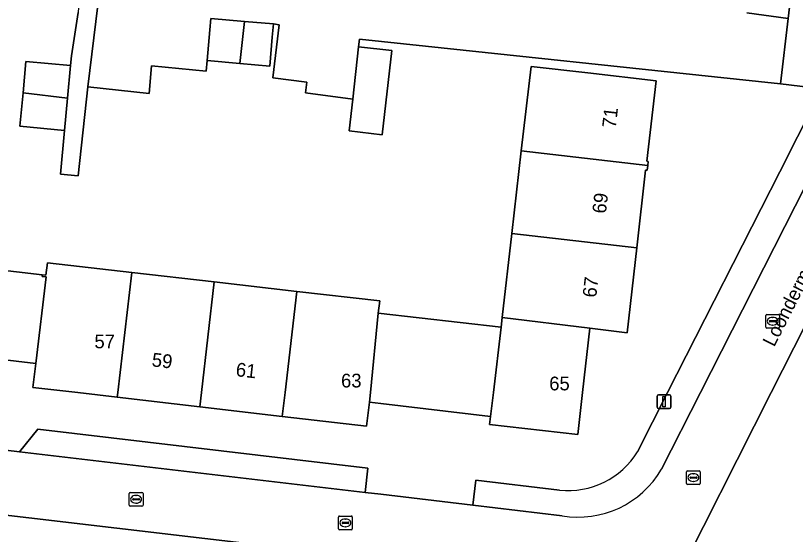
# Model space of a CAD drawing. Extents: x 161241 to 161758, y 384138 to 384885.
# Drawn here: x 161473.4 to 161530.1, y 384489.7 to 384527.4 of the extents above; entities that cross this region are included whole.
import ezdxf

# ---------------------------------------------------------------- set-up
doc = ezdxf.new("R2010")
doc.units = 0
for name, color, linetype in [('IMGEO_Erf', 7, 'Continuous'), ('IMGEO_Kolk', 7, 'Continuous'), ('IMGEO_Lichtmast', 7, 'Continuous'), ('IMGEO_Openbare_ruimte_label', 7, 'Continuous'), ('IMGEO_Pand', 7, 'Continuous'), ('IMGEO_Pand_nummerreeks', 7, 'Continuous'), ('IMGEO_Parkeervlak_open', 7, 'Continuous'), ('IMGEO_Rijbaan_lokaal_open', 7, 'Continuous'), ('IMGEO_Voetpad_open', 7, 'Continuous')]:
    doc.layers.add(name, color=color, linetype=linetype)

msp = doc.modelspace()

# ---------------------------------------------------------------- linework, layer by layer
at = {"layer": 'IMGEO_Erf'}
for points in [[(161523.254, 384566.865), (161544.482, 384564.358), (161544.805, 384567.256), (161545.138, 384570.12), (161546.893, 384585.147), (161552.363, 384584.51), (161557.347, 384583.93), (161554.934, 384563.149), (161549.997, 384563.724), (161547.01, 384536.791), (161539.084, 384521.135), (161528.385, 384500), (161520.975, 384485.363), (161514.621, 384486.15), (161513.81, 384486.25), (161510.292, 384449.829)], [(161526.614, 384527.621), (161529.608, 384527.209), (161533.354, 384558.711)], [(161497.948, 384521.353), (161494.507, 384521.807), (161494.61, 384522.581), (161492.139, 384522.907), (161492.609, 384526.767), (161492.185, 384526.819), (161492.101, 384525.868), (161491.915, 384523.761), (161489.736, 384523.954), (161487.362, 384524.164), (161487.293, 384523.385), (161483.32, 384523.775), (161483.162, 384521.753), (161478.689, 384522.238), (161477.99, 384515.77), (161476.699, 384515.881), (161477.002, 384519.077), (161473.757, 384519.376), (161473.981, 384521.799), (161474.192, 384524.085), (161477.437, 384523.786), (161477.504, 384524.509), (161477.986, 384527.66)], [(161518.656, 384495.69), (161520.844, 384500), (161528.997, 384516.063), (161530.289, 384518.608), (161532.06, 384522.097), (161529.045, 384522.471), (161498.44, 384525.706), (161498.381, 384525.152), (161500.794, 384524.877), (161500.097, 384518.765), (161497.684, 384519.04), (161497.948, 384521.353)], [(161466.833, 384509.551), (161475.383, 384508.568), (161475.645, 384508.538), (161475.751, 384509.452), (161481.888, 384508.746), (161487.887, 384508.056), (161493.887, 384507.366), (161499.919, 384506.672), (161499.806, 384505.78), (161508.732, 384504.753), (161508.814, 384505.467), (161509.517, 384511.579), (161510.209, 384517.593), (161510.915, 384523.734), (161515.039, 384523.257), (161520.008, 384522.683), (161519.33, 384516.828), (161519.434, 384516.821), (161519.396, 384516.532), (161519.349, 384516.181), (161519.244, 384516.192), (161518.598, 384510.53), (161517.893, 384504.356), (161515.201, 384504.684), (161514.662, 384500), (161514.31, 384496.94), (161507.907, 384497.678), (161507.972, 384498.271), (161500, 384499.202), (161499.16, 384499.3), (161498.958, 384497.553), (161492.829, 384498.268), (161486.83, 384498.967), (161480.832, 384499.666), (161477.97, 384500), (161474.702, 384500.381), (161474.911, 384502.113), (161466.108, 384503.152)], [(161456.261, 384497.821), (161473.721, 384495.685), (161475.066, 384497.328), (161499.057, 384494.509), (161498.849, 384492.738), (161500, 384492.603), (161506.677, 384491.817), (161506.891, 384493.621), (161512.994, 384492.896)]]:
    msp.add_lwpolyline(points, dxfattribs=at)
msp.add_arc((161513.606, 384498.79), 5.925, 264.0718, 328.4576, dxfattribs=at)
at = {"layer": 'IMGEO_Kolk'}
for p, q in [((161528.06, 384505.69), (161528.912, 384505.69)), ((161527.985, 384504.764), (161527.985, 384505.616)), ((161528.244, 384505.184), (161528.244, 384505.196)), ((161528.682, 384505.147), (161528.284, 384505.147)), ((161528.287, 384505.233), (161528.685, 384505.233)), ((161528.473, 384505.47), (161528.498, 384505.47)), ((161528.728, 384505.196), (161528.728, 384505.184)), ((161528.986, 384505.616), (161528.986, 384504.764)), ((161528.912, 384504.69), (161528.06, 384504.69)), ((161528.496, 384504.91), (161528.471, 384504.91)), ((161522.219, 384493.388), (161522.219, 384494.24)), ((161522.294, 384494.314), (161523.146, 384494.314)), ((161522.478, 384493.808), (161522.478, 384493.82)), ((161522.521, 384493.857), (161522.919, 384493.857)), ((161522.707, 384494.094), (161522.732, 384494.094)), ((161522.962, 384493.82), (161522.962, 384493.808)), ((161523.22, 384494.24), (161523.22, 384493.388)), ((161523.146, 384493.314), (161522.294, 384493.314)), ((161522.916, 384493.771), (161522.518, 384493.771)), ((161522.73, 384493.534), (161522.705, 384493.534)), ((161481.702, 384491.81), (161481.702, 384492.662)), ((161481.777, 384492.736), (161482.629, 384492.736)), ((161482.703, 384492.662), (161482.703, 384491.81)), ((161481.961, 384492.23), (161481.961, 384492.242)), ((161482.399, 384492.193), (161482.001, 384492.193)), ((161482.004, 384492.279), (161482.402, 384492.279)), ((161482.19, 384492.516), (161482.215, 384492.516)), ((161482.445, 384492.242), (161482.445, 384492.23)), ((161482.629, 384491.736), (161481.777, 384491.736)), ((161482.213, 384491.956), (161482.188, 384491.956)), ((161496.995, 384491.019), (161497.847, 384491.019)), ((161496.92, 384490.093), (161496.92, 384490.945)), ((161497.179, 384490.513), (161497.179, 384490.525)), ((161497.617, 384490.476), (161497.219, 384490.476)), ((161497.222, 384490.562), (161497.62, 384490.562)), ((161497.408, 384490.799), (161497.433, 384490.799)), ((161497.663, 384490.525), (161497.663, 384490.513)), ((161497.921, 384490.945), (161497.921, 384490.093)), ((161497.847, 384490.019), (161496.995, 384490.019)), ((161497.431, 384490.239), (161497.406, 384490.239))]:
    msp.add_line(p, q, dxfattribs=at)
for points in [[(161528.06, 384505.69), (161528.912, 384505.69)], [(161527.985, 384504.764), (161527.985, 384505.616)], [(161528.986, 384505.616), (161528.986, 384504.764)], [(161528.912, 384504.69), (161528.06, 384504.69)], [(161522.219, 384493.388), (161522.219, 384494.24)], [(161522.294, 384494.314), (161523.146, 384494.314)], [(161523.22, 384494.24), (161523.22, 384493.388)], [(161523.146, 384493.314), (161522.294, 384493.314)], [(161481.702, 384491.81), (161481.702, 384492.662)], [(161481.777, 384492.736), (161482.629, 384492.736)], [(161482.703, 384492.662), (161482.703, 384491.81)], [(161482.629, 384491.736), (161481.777, 384491.736)], [(161496.995, 384491.019), (161497.847, 384491.019)], [(161496.92, 384490.093), (161496.92, 384490.945)], [(161497.921, 384490.945), (161497.921, 384490.093)], [(161497.847, 384490.019), (161496.995, 384490.019)]]:
    msp.add_lwpolyline(points, dxfattribs=at)
for centre, radius, start, end in [((161528.062, 384505.614), 0.0765, 91.552, 178.448), ((161528.062, 384505.614), 0.0765, 91.552, 178.448), ((161528.91, 384505.614), 0.0765, 1.552, 88.448), ((161528.91, 384505.614), 0.0765, 1.552, 88.448), ((161528.284, 384505.193), 0.0403, 85.8775, 175.7526), ((161528.281, 384505.183), 0.0366, 178.938, 274.7102), ((161528.685, 384505.19), 0.043, 264.8664, 352.4533), ((161528.689, 384505.195), 0.0386, 1.7309, 96.639), ((161528.062, 384504.766), 0.0765, 181.552, 268.448), ((161528.062, 384504.766), 0.0765, 181.552, 268.448), ((161528.91, 384504.766), 0.0765, 271.552, 358.448), ((161528.91, 384504.766), 0.0765, 271.552, 358.448), ((161522.296, 384494.238), 0.0765, 91.552, 178.448), ((161522.296, 384494.238), 0.0765, 91.552, 178.448), ((161522.518, 384493.817), 0.0403, 85.8775, 175.7526), ((161522.515, 384493.807), 0.0366, 178.938, 274.7102), ((161522.919, 384493.814), 0.043, 264.8664, 352.4533), ((161522.923, 384493.819), 0.0386, 1.7309, 96.639), ((161523.144, 384494.238), 0.0765, 1.552, 88.448), ((161523.144, 384494.238), 0.0765, 1.552, 88.448), ((161522.296, 384493.39), 0.0765, 181.552, 268.448), ((161522.296, 384493.39), 0.0765, 181.552, 268.448), ((161523.144, 384493.39), 0.0765, 271.552, 358.448), ((161523.144, 384493.39), 0.0765, 271.552, 358.448), ((161481.779, 384492.66), 0.0765, 91.552, 178.448), ((161481.779, 384492.66), 0.0765, 91.552, 178.448), ((161482.627, 384492.66), 0.0765, 1.552, 88.448), ((161482.627, 384492.66), 0.0765, 1.552, 88.448), ((161482.001, 384492.239), 0.0403, 85.8775, 175.7526), ((161481.998, 384492.229), 0.0366, 178.938, 274.7102), ((161482.402, 384492.236), 0.043, 264.8664, 352.4533), ((161482.406, 384492.241), 0.0386, 1.7309, 96.639), ((161481.779, 384491.812), 0.0765, 181.552, 268.448), ((161481.779, 384491.812), 0.0765, 181.552, 268.448), ((161482.627, 384491.812), 0.0765, 271.552, 358.448), ((161482.627, 384491.812), 0.0765, 271.552, 358.448), ((161496.997, 384490.943), 0.0765, 91.552, 178.448), ((161496.997, 384490.943), 0.0765, 91.552, 178.448), ((161497.845, 384490.943), 0.0765, 1.552, 88.448), ((161497.845, 384490.943), 0.0765, 1.552, 88.448), ((161497.219, 384490.522), 0.0403, 85.8775, 175.7526), ((161497.216, 384490.512), 0.0366, 178.938, 274.7102), ((161497.62, 384490.519), 0.043, 264.8664, 352.4533), ((161497.624, 384490.524), 0.0386, 1.7309, 96.639), ((161496.997, 384490.095), 0.0765, 181.552, 268.448), ((161496.997, 384490.095), 0.0765, 181.552, 268.448), ((161497.845, 384490.095), 0.0765, 271.552, 358.448), ((161497.845, 384490.095), 0.0765, 271.552, 358.448)]:
    msp.add_arc(centre, radius, start, end, dxfattribs=at)
for centre, major_axis, ratio, start_param, end_param in [((161528.472, 384505.19), (-0.387, 0.002), 0.722429, 4.712389, 7.853982), ((161528.497, 384505.19), (-0.39, 0.002), 0.717154, 1.570796, 4.712389), ((161522.706, 384493.814), (-0.387, 0.002), 0.722429, 4.712389, 7.853982), ((161522.731, 384493.814), (-0.39, 0.002), 0.717154, 1.570796, 4.712389), ((161482.189, 384492.236), (-0.387, 0.002), 0.722429, 4.712389, 7.853982), ((161482.214, 384492.236), (-0.39, 0.002), 0.717154, 1.570796, 4.712389), ((161497.407, 384490.519), (-0.387, 0.002), 0.722429, 4.712389, 7.853982), ((161497.432, 384490.519), (-0.39, 0.002), 0.717154, 1.570796, 4.712389)]:
    msp.add_ellipse(centre, major_axis=major_axis, ratio=ratio, start_param=start_param, end_param=end_param, dxfattribs=at)
at = {"layer": 'IMGEO_Lichtmast'}
for p, q in [((161520.087, 384498.933), (161520.087, 384499.733)), ((161520.087, 384499.733), (161520.087, 384498.933)), ((161520.187, 384499.833), (161520.977, 384499.833)), ((161520.977, 384499.833), (161520.187, 384499.833)), ((161521.077, 384499.733), (161521.077, 384498.933)), ((161521.077, 384498.933), (161521.077, 384499.733)), ((161520.977, 384498.833), (161520.187, 384498.833)), ((161520.187, 384498.833), (161520.977, 384498.833))]:
    msp.add_line(p, q, dxfattribs=at)
msp.add_lwpolyline([(161520.507, 384499.708), (161520.657, 384499.708), (161520.657, 384498.958), (161520.507, 384498.958), (161520.507, 384499.708)], dxfattribs=at)
for centre, start, end in [((161520.187, 384499.733), 90, 180), ((161520.187, 384499.733), 90, 180), ((161520.977, 384499.733), 0, 90), ((161520.977, 384499.733), 360, 90), ((161520.187, 384498.933), 180, 270), ((161520.187, 384498.933), 180, 270), ((161520.977, 384498.933), 270, 0), ((161520.977, 384498.933), 270, 0)]:
    msp.add_arc(centre, 0.1, start, end, dxfattribs=at)
at = {"layer": 'IMGEO_Pand'}
for points in [[(161490.091, 384527.004), (161487.632, 384527.222), (161487.558, 384526.386), (161487.362, 384524.164), (161489.736, 384523.954)], [(161492.101, 384525.868), (161492.185, 384526.819), (161490.091, 384527.004), (161489.736, 384523.954), (161491.915, 384523.761)], [(161500.794, 384524.877), (161498.381, 384525.152), (161497.948, 384521.353), (161497.684, 384519.04), (161500.097, 384518.765)], [(161477.437, 384523.786), (161474.192, 384524.085), (161473.981, 384521.799), (161477.219, 384521.424)], [(161519.396, 384516.532), (161519.434, 384516.821), (161519.33, 384516.828), (161520.008, 384522.683), (161515.039, 384523.257), (161510.915, 384523.734), (161510.209, 384517.593)], [(161473.757, 384519.376), (161477.002, 384519.077), (161477.219, 384521.424), (161473.981, 384521.799)], [(161510.209, 384517.593), (161509.517, 384511.579), (161518.598, 384510.53), (161519.244, 384516.192), (161519.349, 384516.181), (161519.396, 384516.532)], [(161515.201, 384504.684), (161517.893, 384504.356), (161518.598, 384510.53), (161509.517, 384511.579), (161508.814, 384505.467)], [(161475.383, 384508.568), (161466.833, 384509.551), (161466.108, 384503.152), (161474.911, 384502.113), (161475.672, 384508.413), (161475.37, 384508.45)], [(161475.37, 384508.45), (161475.672, 384508.413), (161474.911, 384502.113), (161474.702, 384500.381), (161477.97, 384500), (161480.832, 384499.666), (161480.871, 384500), (161481.888, 384508.746), (161475.751, 384509.452), (161475.645, 384508.538), (161475.383, 384508.568)], [(161480.832, 384499.666), (161486.83, 384498.967), (161486.95, 384500), (161487.887, 384508.056), (161481.888, 384508.746), (161480.871, 384500)], [(161493.887, 384507.366), (161487.887, 384508.056), (161486.95, 384500), (161486.83, 384498.967), (161492.829, 384498.268), (161493.03, 384500)], [(161493.03, 384500), (161492.829, 384498.268), (161498.958, 384497.553), (161499.16, 384499.3), (161499.235, 384500), (161499.806, 384505.78), (161499.919, 384506.672), (161493.887, 384507.366)], [(161508.177, 384500), (161508.732, 384504.753), (161499.806, 384505.78), (161499.235, 384500), (161499.16, 384499.3), (161500, 384499.202), (161507.972, 384498.271)], [(161507.972, 384498.271), (161507.907, 384497.678), (161514.31, 384496.94), (161514.662, 384500), (161515.201, 384504.684), (161508.814, 384505.467), (161508.732, 384504.753), (161508.177, 384500)]]:
    msp.add_lwpolyline(points, close=True, dxfattribs=at)
at = {"layer": 'IMGEO_Parkeervlak_open'}
msp.add_lwpolyline([(161498.849, 384492.738), (161499.057, 384494.509), (161475.066, 384497.328), (161473.721, 384495.685)], close=True, dxfattribs=at)
at = {"layer": 'IMGEO_Rijbaan_lokaal_open'}
msp.add_lwpolyline([(161549.997, 384563.724), (161552.363, 384584.51), (161546.893, 384585.147), (161545.138, 384570.12), (161544.805, 384567.256), (161544.482, 384564.358), (161544.235, 384562.197), (161526.561, 384564.282), (161512.889, 384565.866), (161500, 384567.378), (161464.869, 384571.501), (161464.362, 384566.766), (161482.25, 384564.675), (161500, 384562.593), (161511.694, 384561.211), (161511.799, 384561.199), (161533.354, 384558.711), (161529.608, 384527.209), (161529.045, 384522.471), (161532.06, 384522.097), (161534.304, 384521.808), (161539.084, 384521.135), (161547.01, 384536.791)], close=True, dxfattribs=at)
for points in [[(161480.018, 384533.151), (161478.689, 384522.238), (161483.162, 384521.753), (161483.32, 384523.775), (161487.293, 384523.385), (161487.362, 384524.164), (161487.558, 384526.386), (161487.632, 384527.222), (161490.091, 384527.004), (161492.185, 384526.819), (161492.609, 384526.767), (161492.139, 384522.907), (161494.61, 384522.581), (161494.507, 384521.807), (161497.948, 384521.353), (161498.381, 384525.152), (161498.44, 384525.706), (161529.045, 384522.471), (161529.608, 384527.209), (161526.614, 384527.621)], [(161539.084, 384521.135), (161534.304, 384521.808), (161532.188, 384517.643), (161530.896, 384515.099), (161523.226, 384500), (161520.396, 384494.429)], [(161513.174, 384491.028), (161506.677, 384491.817), (161500, 384492.603), (161498.849, 384492.738), (161473.721, 384495.685), (161456.261, 384497.821), (161442.259, 384499.359), (161436.769, 384500), (161430.603, 384500.72), (161430.519, 384500), (161430.062, 384496.065), (161448.776, 384493.891), (161500, 384487.889), (161510.654, 384486.641), (161513.81, 384486.25), (161514.621, 384486.15), (161520.975, 384485.363), (161528.385, 384500), (161539.084, 384521.135)]]:
    msp.add_lwpolyline(points, dxfattribs=at)
msp.add_arc((161514.325, 384497.952), 7.019, 260.5591, 329.8745, dxfattribs=at)
at = {"layer": 'IMGEO_Voetpad_open'}
for points in [[(161480.018, 384533.151), (161480.929, 384533.054), (161481.372, 384536.621), (161481.755, 384539.706), (161479.365, 384539.957), (161479.31, 384539.433), (161479.067, 384537.13), (161478.149, 384529.998), (161478.133, 384529.762), (161477.986, 384527.66), (161477.504, 384524.509), (161477.437, 384523.786), (161477.219, 384521.424), (161477.002, 384519.077), (161476.699, 384515.881), (161477.99, 384515.77), (161478.689, 384522.238)], [(161430.062, 384496.065), (161427.321, 384496.383), (161396.178, 384500), (161357.097, 384504.581), (161354.376, 384504.9), (161340.82, 384506.489), (161340.647, 384506.515), (161340.403, 384504.377), (161341.704, 384504.225), (161377.935, 384500), (161395.453, 384497.957), (161401.111, 384497.3), (161421.466, 384494.929), (161433, 384493.585), (161437.975, 384493.006), (161442.515, 384492.47), (161448.511, 384491.779), (161454.323, 384491.094), (161500, 384485.79), (161510.344, 384484.589), (161510.654, 384486.641), (161500, 384487.889), (161448.776, 384493.891)]]:
    msp.add_lwpolyline(points, close=True, dxfattribs=at)
for points in [[(161534.304, 384521.808), (161532.06, 384522.097), (161530.289, 384518.608), (161528.997, 384516.063), (161520.844, 384500), (161518.656, 384495.69)], [(161520.396, 384494.429), (161523.226, 384500), (161530.896, 384515.099), (161532.188, 384517.643), (161534.304, 384521.808)], [(161512.994, 384492.896), (161506.891, 384493.621), (161506.677, 384491.817), (161513.174, 384491.028)]]:
    msp.add_lwpolyline(points, dxfattribs=at)
for centre, radius, start, end in [((161513.606, 384498.79), 5.925, 264.0718, 328.4576), ((161514.325, 384497.952), 7.019, 260.5591, 329.8745)]:
    msp.add_arc(centre, radius, start, end, dxfattribs=at)

# ---------------------------------------------------------------- texts
at = {"layer": 'IMGEO_Openbare_ruimte_label'}
msp.add_text('Loondermolen', height=1, rotation=63.1275, dxfattribs=at).set_placement((161528.591, 384503.268))
at = {"layer": 'IMGEO_Pand_nummerreeks'}
for s, rotation, p in [('71', 83.417, (161517.071, 384519.209)), ('69', 83.417, (161516.353, 384512.988)), ('67', 83.417, (161515.648, 384506.879)), ('59', 353.3533, (161483.302, 384501.915)), ('61', 353.3533, (161489.412, 384501.203))]:
    msp.add_text(s, height=1, rotation=rotation, dxfattribs=at).set_placement(p)
for s, p in [('57', (161479.173, 384503.221)), ('63', (161497.103, 384500.372)), ('65', (161512.24, 384500.161))]:
    msp.add_text(s, height=1, dxfattribs=at).set_placement(p)

doc.saveas('drawing.dxf')
